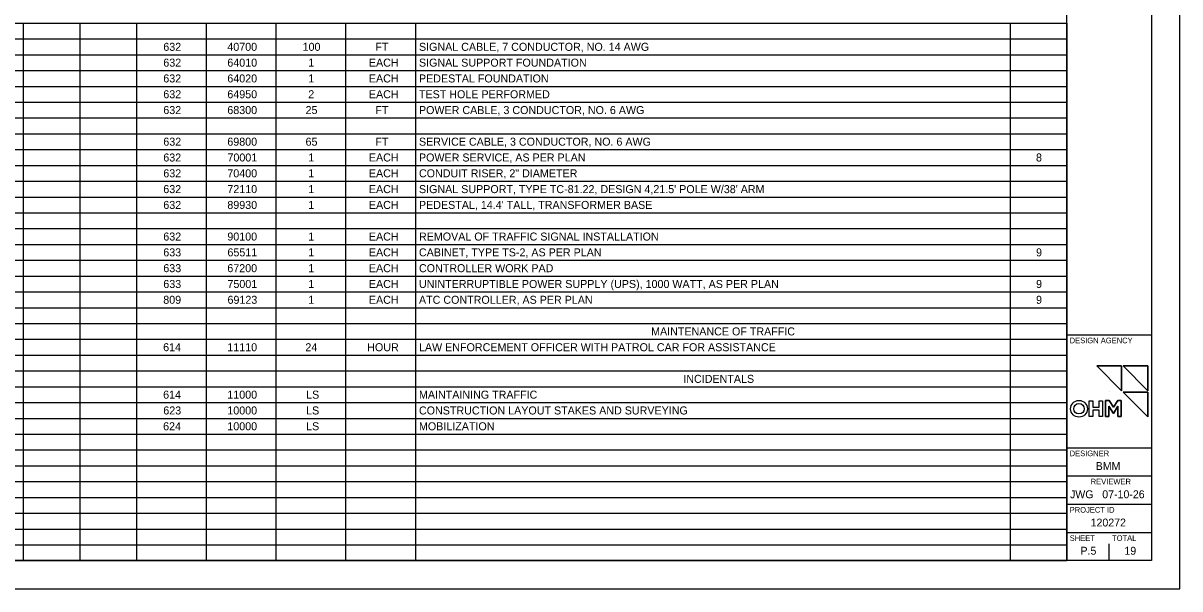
# Model space of a CAD drawing. Extents: x 0 to 34, y 0 to 22.
# Drawn here: x 13.53 to 34, y 0 to 10.02 of the extents above; entities that cross this region are included whole.
import ezdxf

# ---------------------------------------------------------------- set-up
doc = ezdxf.new("R2010")
doc.units = 0
for name, color, linetype in [('Default', 7, 'Continuous'), ('SH_Border', 7, 'Continuous'), ('SH_Cut_Line', 7, 'Continuous'), ('SH_Data', 7, 'Continuous'), ('TX_P_Misc', 7, 'Continuous')]:
    doc.layers.add(name, color=color, linetype=linetype)

msp = doc.modelspace()

# ---------------------------------------------------------------- linework, layer by layer
at = {"layer": 'Default'}
for p, q in [((12.528, 10.02), (13.53, 10.02)), ((13.53, 10.02), (15.535, 10.02)), ((13.53, 10.02), (13.53, 9.74)), ((14.533, 10.02), (14.533, 9.74)), ((15.535, 10.02), (32, 10.02)), ((15.535, 10.02), (15.535, 9.74)), ((16.769, 10.02), (16.769, 9.74)), ((18.003, 10.02), (18.003, 9.74)), ((19.237, 10.02), (19.237, 9.74)), ((20.471, 10.02), (20.471, 9.74)), ((30.997, 10.02), (30.997, 9.74)), ((32, 10.02), (32, 9.74)), ((12.528, 9.74), (13.53, 9.74)), ((13.53, 9.74), (15.535, 9.74)), ((13.53, 9.74), (13.53, 8.9)), ((14.533, 9.74), (14.533, 8.9)), ((15.535, 9.74), (32, 9.74)), ((15.535, 9.74), (15.535, 8.9)), ((16.769, 9.74), (16.769, 8.9)), ((18.003, 9.74), (18.003, 8.9)), ((19.237, 9.74), (19.237, 8.9)), ((20.471, 9.74), (20.471, 8.9)), ((30.997, 9.74), (30.997, 8.9)), ((32, 9.74), (32, 8.9)), ((12.528, 9.46), (13.53, 9.46)), ((13.53, 9.46), (15.535, 9.46)), ((15.535, 9.46), (32, 9.46)), ((12.528, 9.18), (13.53, 9.18)), ((13.53, 9.18), (15.535, 9.18)), ((15.535, 9.18), (32, 9.18)), ((12.528, 8.9), (13.53, 8.9)), ((13.53, 8.9), (15.535, 8.9)), ((13.53, 8.9), (13.53, 8.34)), ((14.533, 8.9), (14.533, 8.34)), ((15.535, 8.9), (32, 8.9)), ((15.535, 8.9), (15.535, 8.34)), ((16.769, 8.9), (16.769, 8.34)), ((18.003, 8.9), (18.003, 8.34)), ((19.237, 8.9), (19.237, 8.34)), ((20.471, 8.9), (20.471, 8.34)), ((30.997, 8.9), (30.997, 8.34)), ((32, 8.9), (32, 8.34)), ((12.528, 8.62), (13.53, 8.62)), ((13.53, 8.62), (15.535, 8.62)), ((15.535, 8.62), (32, 8.62)), ((12.528, 8.34), (13.53, 8.34)), ((13.53, 8.34), (15.535, 8.34)), ((13.53, 8.34), (13.53, 7.5)), ((14.533, 8.34), (14.533, 7.5)), ((15.535, 8.34), (32, 8.34)), ((15.535, 8.34), (15.535, 7.5)), ((16.769, 8.34), (16.769, 7.5)), ((18.003, 8.34), (18.003, 7.5)), ((19.237, 8.34), (19.237, 7.5)), ((20.471, 8.34), (20.471, 7.5)), ((30.997, 8.34), (30.997, 7.5)), ((32, 8.34), (32, 7.5)), ((12.528, 8.06), (13.53, 8.06)), ((13.53, 8.06), (15.535, 8.06)), ((15.535, 8.06), (32, 8.06)), ((12.528, 7.78), (13.53, 7.78)), ((13.53, 7.78), (15.535, 7.78)), ((15.535, 7.78), (32, 7.78)), ((12.528, 7.5), (13.53, 7.5)), ((13.53, 7.5), (15.535, 7.5)), ((13.53, 7.5), (13.53, 6.94)), ((14.533, 7.5), (14.533, 6.94)), ((15.535, 7.5), (32, 7.5)), ((15.535, 7.5), (15.535, 6.94)), ((16.769, 7.5), (16.769, 6.94)), ((18.003, 7.5), (18.003, 6.94)), ((19.237, 7.5), (19.237, 6.94)), ((20.471, 7.5), (20.471, 6.94)), ((30.997, 7.5), (30.997, 6.94)), ((32, 7.5), (32, 6.94)), ((12.528, 7.22), (13.53, 7.22)), ((13.53, 7.22), (15.535, 7.22)), ((15.535, 7.22), (32, 7.22)), ((12.528, 6.94), (13.53, 6.94)), ((13.53, 6.94), (15.535, 6.94)), ((13.53, 6.94), (13.53, 6.1)), ((14.533, 6.94), (14.533, 6.1)), ((15.535, 6.94), (32, 6.94)), ((15.535, 6.94), (15.535, 6.1)), ((16.769, 6.94), (16.769, 6.1)), ((18.003, 6.94), (18.003, 6.1)), ((19.237, 6.94), (19.237, 6.1)), ((20.471, 6.94), (20.471, 6.1)), ((30.997, 6.94), (30.997, 6.1)), ((32, 6.94), (32, 6.1)), ((12.528, 6.66), (13.53, 6.66)), ((13.53, 6.66), (15.535, 6.66)), ((15.535, 6.66), (32, 6.66)), ((12.528, 6.38), (13.53, 6.38)), ((13.53, 6.38), (15.535, 6.38)), ((15.535, 6.38), (32, 6.38)), ((12.528, 6.1), (13.53, 6.1)), ((13.53, 6.1), (15.535, 6.1)), ((13.53, 6.1), (13.53, 4.98)), ((14.533, 6.1), (14.533, 4.98)), ((15.535, 6.1), (32, 6.1)), ((15.535, 6.1), (15.535, 4.98)), ((16.769, 6.1), (16.769, 4.98)), ((18.003, 6.1), (18.003, 4.98)), ((19.237, 6.1), (19.237, 4.98)), ((20.471, 6.1), (20.471, 4.98)), ((30.997, 6.1), (30.997, 4.98)), ((32, 6.1), (32, 4.98)), ((12.528, 5.82), (13.53, 5.82)), ((13.53, 5.82), (15.535, 5.82)), ((15.535, 5.82), (32, 5.82)), ((12.528, 5.54), (13.53, 5.54)), ((13.53, 5.54), (15.535, 5.54)), ((15.535, 5.54), (32, 5.54)), ((12.528, 5.26), (13.53, 5.26)), ((13.53, 5.26), (15.535, 5.26)), ((15.535, 5.26), (32, 5.26)), ((12.528, 4.98), (13.53, 4.98)), ((13.53, 4.98), (15.535, 4.98)), ((13.53, 4.98), (13.53, 4.7)), ((14.533, 4.98), (14.533, 4.7)), ((15.535, 4.98), (32, 4.98)), ((15.535, 4.98), (15.535, 4.7)), ((16.769, 4.98), (16.769, 4.7)), ((18.003, 4.98), (18.003, 4.7)), ((19.237, 4.98), (19.237, 4.7)), ((20.471, 4.98), (20.471, 4.7)), ((30.997, 4.98), (30.997, 4.7)), ((32, 4.98), (32, 4.7)), ((12.528, 4.7), (13.53, 4.7)), ((13.53, 4.7), (15.535, 4.7)), ((13.53, 4.7), (13.53, 3.58)), ((14.533, 4.7), (14.533, 3.58)), ((15.535, 4.7), (32, 4.7)), ((15.535, 4.7), (15.535, 3.58)), ((16.769, 4.7), (16.769, 3.58)), ((18.003, 4.7), (18.003, 3.58)), ((19.237, 4.7), (19.237, 3.58)), ((20.471, 4.7), (20.471, 3.58)), ((30.997, 4.7), (30.997, 3.58)), ((32, 4.7), (32, 3.58)), ((12.528, 4.42), (13.53, 4.42)), ((13.53, 4.42), (15.535, 4.42)), ((15.535, 4.42), (32, 4.42)), ((12.528, 4.14), (13.53, 4.14)), ((13.53, 4.14), (15.535, 4.14)), ((15.535, 4.14), (32, 4.14)), ((12.528, 3.86), (13.53, 3.86)), ((13.53, 3.86), (15.535, 3.86)), ((15.535, 3.86), (32, 3.86)), ((12.528, 3.58), (13.53, 3.58)), ((13.53, 3.58), (15.535, 3.58)), ((13.53, 3.58), (13.53, 3.3)), ((14.533, 3.58), (14.533, 3.3)), ((15.535, 3.58), (32, 3.58)), ((15.535, 3.58), (15.535, 3.3)), ((16.769, 3.58), (16.769, 3.3)), ((18.003, 3.58), (18.003, 3.3)), ((19.237, 3.58), (19.237, 3.3)), ((20.471, 3.58), (20.471, 3.3)), ((30.997, 3.58), (30.997, 3.3)), ((32, 3.58), (32, 3.3)), ((12.528, 3.3), (13.53, 3.3)), ((13.53, 3.3), (15.535, 3.3)), ((13.53, 3.3), (13.53, 2.18)), ((14.533, 3.3), (14.533, 2.18)), ((15.535, 3.3), (32, 3.3)), ((15.535, 3.3), (15.535, 2.18)), ((16.769, 3.3), (16.769, 2.18)), ((18.003, 3.3), (18.003, 2.18)), ((19.237, 3.3), (19.237, 2.18)), ((20.471, 3.3), (20.471, 2.18)), ((30.997, 3.3), (30.997, 2.18)), ((32, 3.3), (32, 2.18)), ((12.528, 3.02), (13.53, 3.02)), ((13.53, 3.02), (15.535, 3.02)), ((15.535, 3.02), (32, 3.02)), ((12.528, 2.74), (13.53, 2.74)), ((13.53, 2.74), (15.535, 2.74)), ((15.535, 2.74), (32, 2.74)), ((12.528, 2.46), (13.53, 2.46)), ((13.53, 2.46), (15.535, 2.46)), ((15.535, 2.46), (32, 2.46)), ((12.528, 2.18), (13.53, 2.18)), ((13.53, 2.18), (15.535, 2.18)), ((13.53, 2.18), (13.53, 1.9)), ((14.533, 2.18), (14.533, 1.9)), ((15.535, 2.18), (32, 2.18)), ((15.535, 2.18), (15.535, 1.9)), ((16.769, 2.18), (16.769, 1.9)), ((18.003, 2.18), (18.003, 1.9)), ((19.237, 2.18), (19.237, 1.9)), ((20.471, 2.18), (20.471, 1.9)), ((30.997, 2.18), (30.997, 1.9)), ((32, 2.18), (32, 1.9)), ((12.528, 1.9), (13.53, 1.9)), ((13.53, 1.9), (15.535, 1.9)), ((13.53, 1.9), (13.53, 0.78)), ((14.533, 1.9), (14.533, 0.78)), ((15.535, 1.9), (32, 1.9)), ((15.535, 1.9), (15.535, 0.78)), ((16.769, 1.9), (16.769, 0.78)), ((18.003, 1.9), (18.003, 0.78)), ((19.237, 1.9), (19.237, 0.78)), ((20.471, 1.9), (20.471, 0.78)), ((30.997, 1.9), (30.997, 0.78)), ((32, 1.9), (32, 0.78)), ((12.528, 1.62), (13.53, 1.62)), ((13.53, 1.62), (15.535, 1.62)), ((15.535, 1.62), (32, 1.62)), ((12.528, 1.34), (13.53, 1.34)), ((13.53, 1.34), (15.535, 1.34)), ((15.535, 1.34), (32, 1.34)), ((12.528, 1.06), (13.53, 1.06)), ((13.53, 1.06), (15.535, 1.06)), ((15.535, 1.06), (32, 1.06)), ((12.528, 0.78), (13.53, 0.78)), ((13.53, 0.78), (15.535, 0.78)), ((13.53, 0.78), (13.53, 0.5)), ((14.533, 0.78), (14.533, 0.5)), ((15.535, 0.78), (32, 0.78)), ((15.535, 0.78), (15.535, 0.5)), ((16.769, 0.78), (16.769, 0.5)), ((18.003, 0.78), (18.003, 0.5)), ((19.237, 0.78), (19.237, 0.5)), ((20.471, 0.78), (20.471, 0.5)), ((30.997, 0.78), (30.997, 0.5)), ((32, 0.78), (32, 0.5)), ((12.528, 0.5), (13.53, 0.5)), ((13.53, 0.5), (15.535, 0.5)), ((15.535, 0.5), (32, 0.5))]:
    msp.add_line(p, q, dxfattribs=at)
for points in [[(32.966, 3.948), (32.966, 3.51), (32.53, 3.948)], [(33.433, 3.948), (33.433, 3.51), (32.997, 3.948)], [(33.433, 3.483), (33.433, 3.045), (32.997, 3.483)], [(32.397, 3.333), (32.457, 3.333), (32.457, 3.22), (32.571, 3.22), (32.571, 3.333), (32.631, 3.333), (32.631, 3.052), (32.571, 3.052), (32.571, 3.166), (32.457, 3.166), (32.457, 3.052), (32.397, 3.052)], [(32.9, 3.335), (32.963, 3.335), (32.963, 3.052), (32.903, 3.052), (32.903, 3.233), (32.824, 3.108), (32.745, 3.233), (32.745, 3.052), (32.685, 3.052), (32.685, 3.335), (32.748, 3.335), (32.824, 3.216)]]:
    msp.add_lwpolyline(points, close=True, dxfattribs=at)
at = {"layer": 'SH_Border'}
for p, q in [((32, 0.5), (32, 21.5)), ((32, 4.5), (33.5, 4.5)), ((32, 2.5), (33.5, 2.5)), ((32, 2), (33.5, 2)), ((32, 1.5), (33.5, 1.5)), ((32, 1), (33.5, 1))]:
    msp.add_line(p, q, dxfattribs=at)
msp.add_lwpolyline([(1.5, 21.5), (33.5, 21.5), (33.5, 0.5), (1.5, 0.5)], close=True, dxfattribs=at)
at = {"layer": 'SH_Cut_Line'}
msp.add_lwpolyline([(0, 0), (34, 0), (34, 22), (0, 22)], close=True, dxfattribs=at)
at = {"layer": 'SH_Data'}
for p, q in [((32.75, 3.5), (32.75, 3.5)), ((32.375, 0.675), (32.375, 0.675)), ((32.75, 0.5), (32.75, 0.8))]:
    msp.add_line(p, q, dxfattribs=at)
at = {"layer": 'TX_P_Misc'}
for p, q in [((32.745, 3.052), (32.745, 3.233)), ((32.745, 3.233), (32.824, 3.108)), ((32.824, 3.108), (32.903, 3.233)), ((32.903, 3.233), (32.903, 3.052))]:
    msp.add_line(p, q, dxfattribs=at)
for points in [[(32.53, 3.948), (32.966, 3.51), (32.966, 3.948), (32.53, 3.948)], [(32.997, 3.948), (33.433, 3.51), (33.433, 3.948), (32.997, 3.948)], [(32.997, 3.483), (33.433, 3.045), (33.433, 3.483), (32.997, 3.483)], [(32.824, 3.216), (32.748, 3.335), (32.685, 3.335), (32.685, 3.052), (32.745, 3.052)], [(32.903, 3.052), (32.963, 3.052), (32.963, 3.335), (32.9, 3.335), (32.824, 3.216)]]:
    msp.add_lwpolyline(points, dxfattribs=at)
msp.add_lwpolyline([(32.397, 3.333), (32.457, 3.333), (32.457, 3.22), (32.571, 3.22), (32.571, 3.333), (32.631, 3.333), (32.631, 3.052), (32.571, 3.052), (32.571, 3.166), (32.457, 3.166), (32.457, 3.052), (32.397, 3.052)], close=True, dxfattribs=at)
for radius in [0.148, 0.148, 0.0927, 0.0927]:
    msp.add_circle((32.215, 3.19), radius, dxfattribs=at)

# ---------------------------------------------------------------- texts
at = {"layer": 'Default'}
for s, height, p in [('632', 0.1417, (16.011, 9.529)), ('40700', 0.1417, (17.144, 9.529)), ('100', 0.1417, (18.476, 9.529)), ('FT', 0.1417, (19.763, 9.529)), ('SIGNAL CABLE, 7 CONDUCTOR, NO. 14 AWG', 0.14166, (20.535, 9.529)), ('632', 0.1417, (16.011, 9.249)), ('64010', 0.1417, (17.144, 9.249)), ('1', 0.142, (18.576, 9.249)), ('EACH', 0.1417, (19.649, 9.249)), ('SIGNAL SUPPORT FOUNDATION', 0.14166, (20.535, 9.249)), ('632', 0.1417, (16.011, 8.969)), ('64020', 0.1417, (17.144, 8.969)), ('1', 0.142, (18.576, 8.969)), ('EACH', 0.1417, (19.649, 8.969)), ('PEDESTAL FOUNDATION', 0.14166, (20.535, 8.969)), ('632', 0.1417, (16.011, 8.689)), ('64950', 0.1417, (17.144, 8.689)), ('2', 0.142, (18.576, 8.689)), ('EACH', 0.1417, (19.649, 8.689)), ('TEST HOLE PERFORMED', 0.14166, (20.535, 8.689)), ('632', 0.1417, (16.011, 8.409)), ('68300', 0.1417, (17.144, 8.409)), ('25', 0.1417, (18.528, 8.409)), ('FT', 0.1417, (19.763, 8.409)), ('POWER CABLE, 3 CONDUCTOR, NO. 6 AWG', 0.14166, (20.535, 8.409)), ('632', 0.1417, (16.011, 7.849)), ('69800', 0.1417, (17.144, 7.849)), ('65', 0.1417, (18.528, 7.849)), ('FT', 0.1417, (19.763, 7.849)), ('SERVICE CABLE, 3 CONDUCTOR, NO. 6 AWG', 0.14166, (20.535, 7.849)), ('632', 0.1417, (16.011, 7.569)), ('70001', 0.1417, (17.146, 7.569)), ('1', 0.142, (18.576, 7.569)), ('EACH', 0.1417, (19.649, 7.569)), ('POWER SERVICE, AS PER PLAN', 0.14166, (20.535, 7.569)), ('8', 0.142, (31.454, 7.569)), ('632', 0.1417, (16.011, 7.289)), ('70400', 0.1417, (17.144, 7.289)), ('1', 0.142, (18.576, 7.289)), ('EACH', 0.1417, (19.649, 7.289)), ('CONDUIT RISER, 2" DIAMETER', 0.14166, (20.535, 7.289)), ('632', 0.1417, (16.011, 7.009)), ('72110', 0.1417, (17.144, 7.009)), ('1', 0.142, (18.576, 7.009)), ('EACH', 0.1417, (19.649, 7.009)), ("SIGNAL SUPPORT, TYPE TC-81.22, DESIGN 4,21.5' POLE W/38' ARM", 0.14166, (20.535, 7.009)), ('632', 0.1417, (16.011, 6.729)), ('89930', 0.1417, (17.144, 6.729)), ('1', 0.142, (18.576, 6.729)), ('EACH', 0.1417, (19.649, 6.729)), ("PEDESTAL, 14.4' TALL, TRANSFORMER BASE", 0.14166, (20.535, 6.729)), ('632', 0.1417, (16.011, 6.169)), ('90100', 0.1417, (17.144, 6.169)), ('1', 0.142, (18.576, 6.169)), ('EACH', 0.1417, (19.649, 6.169)), ('REMOVAL OF TRAFFIC SIGNAL INSTALLATION', 0.14166, (20.535, 6.169)), ('633', 0.1417, (16.011, 5.889)), ('65511', 0.1417, (17.146, 5.889)), ('1', 0.142, (18.576, 5.889)), ('EACH', 0.1417, (19.649, 5.889)), ('CABINET, TYPE TS-2, AS PER PLAN', 0.14166, (20.535, 5.889)), ('9', 0.142, (31.455, 5.889)), ('633', 0.1417, (16.011, 5.609)), ('67200', 0.1417, (17.144, 5.609)), ('1', 0.142, (18.576, 5.609)), ('EACH', 0.1417, (19.649, 5.609)), ('CONTROLLER WORK PAD', 0.14166, (20.535, 5.609)), ('633', 0.1417, (16.011, 5.329)), ('75001', 0.1417, (17.146, 5.329)), ('1', 0.142, (18.576, 5.329)), ('EACH', 0.1417, (19.649, 5.329)), ('UNINTERRUPTIBLE POWER SUPPLY (UPS), 1000 WATT, AS PER PLAN', 0.14166, (20.535, 5.329)), ('9', 0.142, (31.455, 5.329)), ('809', 0.1417, (16.01, 5.049)), ('69123', 0.1417, (17.147, 5.049)), ('1', 0.142, (18.576, 5.049)), ('EACH', 0.1417, (19.649, 5.049)), ('ATC CONTROLLER, AS PER PLAN', 0.14166, (20.535, 5.049)), ('9', 0.142, (31.455, 5.049)), ('MAINTENANCE OF TRAFFIC', 0.14166, (24.643, 4.489)), ('614', 0.1417, (16.008, 4.209)), ('11110', 0.1417, (17.144, 4.209)), ('24', 0.1417, (18.525, 4.209)), ('HOUR', 0.1417, (19.619, 4.209)), ('LAW ENFORCEMENT OFFICER WITH PATROL CAR FOR ASSISTANCE', 0.14166, (20.535, 4.209)), ('INCIDENTALS', 0.14166, (25.213, 3.649)), ('614', 0.1417, (16.008, 3.369)), ('11000', 0.1417, (17.144, 3.369)), ('LS', 0.1417, (18.538, 3.369)), ('MAINTAINING TRAFFIC', 0.14166, (20.535, 3.369)), ('623', 0.1417, (16.011, 3.089)), ('10000', 0.1417, (17.144, 3.089)), ('LS', 0.1417, (18.538, 3.089)), ('CONSTRUCTION LAYOUT STAKES AND SURVEYING', 0.14166, (20.535, 3.089)), ('624', 0.1417, (16.008, 2.809)), ('10000', 0.1417, (17.144, 2.809)), ('LS', 0.1417, (18.538, 2.809)), ('MOBILIZATION', 0.14166, (20.535, 2.809))]:
    msp.add_text(s, height=height, dxfattribs=at).set_placement(p)
at = {"layer": 'SH_Data'}
for s, height, p in [('DESIGN AGENCY', 0.1, (32.05, 4.35)), ('DESIGNER', 0.1, (32.05, 2.35)), ('BMM', 0.14, (32.511, 2.105)), ('REVIEWER', 0.1, (32.422, 1.85)), ('JWG', 0.14, (32.056, 1.605)), ('07-10-26', 0.14, (32.627, 1.605)), ('PROJECT ID', 0.1, (32.05, 1.35)), ('120272', 0.14, (32.421, 1.105)), ('SHEET', 0.1, (32.05, 0.85)), ('TOTAL', 0.1, (32.8, 0.85)), ('P.5', 0.14, (32.241, 0.605)), ('19', 0.14, (33.019, 0.605))]:
    msp.add_text(s, height=height, dxfattribs=at).set_placement(p)

doc.saveas('drawing.dxf')
